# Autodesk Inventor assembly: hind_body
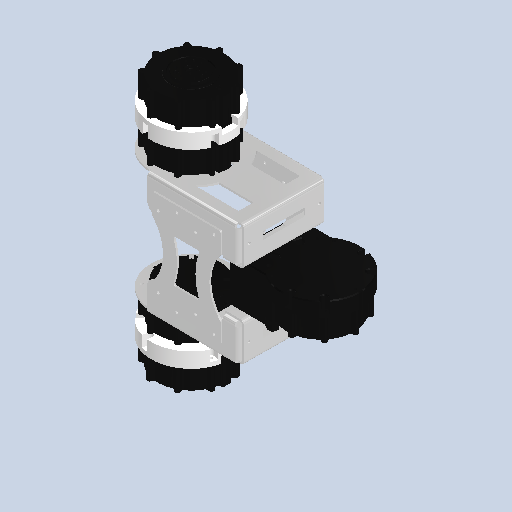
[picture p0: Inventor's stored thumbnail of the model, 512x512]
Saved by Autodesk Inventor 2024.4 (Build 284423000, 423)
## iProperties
Created: 2026-01
Part Number: hind_body
Document SubType Name: Assembly
Designer: AdminForWorker
Title: hind_body v18
Author: AdminForWorker
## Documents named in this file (7)
- c:\worker\convert-fusion-r06-cosv3\tmp\job-1\14\temp\files\7069be28-f26d-4d32-a85d-de0caccc6a05\hind_body v18.iam
- c:\worker\convert-fusion-r06-cosv3\tmp\job-1\14\temp\files\7069be28-f26d-4d32-a85d-de0caccc6a05\body_assembly.iam
- c:\worker\convert-fusion-r06-cosv3\tmp\job-1\14\temp\files\7069be28-f26d-4d32-a85d-de0caccc6a05\leg_connector v1.ipt
- c:\worker\convert-fusion-r06-cosv3\tmp\job-1\14\temp\files\7069be28-f26d-4d32-a85d-de0caccc6a05\CyberGear.ipt
- c:\worker\convert-fusion-r06-cosv3\tmp\job-1\14\temp\files\7069be28-f26d-4d32-a85d-de0caccc6a05\CyberGear (1).ipt
- c:\worker\convert-fusion-r06-cosv3\tmp\job-1\14\temp\files\7069be28-f26d-4d32-a85d-de0caccc6a05\CyberGear (2).ipt
- c:\worker\convert-fusion-r06-cosv3\tmp\job-1\14\temp\files\7069be28-f26d-4d32-a85d-de0caccc6a05\hind_spine v1.iam
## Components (8 placed, 6 different names)
1. body_assembly:1 [sub-assembly]
2. leg_connector v1:1
3. CyberGear:1
4. CyberGear:2
5. CyberGear (1):1
6. CyberGear (2):1
7. leg_connector v1:2
8. hind_spine v1:1 [sub-assembly]
